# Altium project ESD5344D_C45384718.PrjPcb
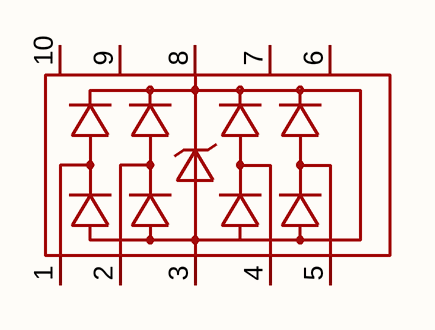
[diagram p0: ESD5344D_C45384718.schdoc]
1 sheet, 1 parts. Net scope: global (net labels, ports and power ports of the same name join across sheets).

## Sheet ESD5344D_C45384718.schdoc
size 127 x 101 mm

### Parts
D?  esd5344d_c45384718  [DFN2510-10_L2.5-W1.0-P0.50-BL]  (value not drawn)

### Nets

Not connected (* = marked no-connect by the designer): D? 1 2 3 4 5 6 7 8 9 10

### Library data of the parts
D? = esd5344d_c45384718: 反向截止电压(Vrwm):5V;钳位电压:15V;击穿电压(VBR):9V;; Manufacturer: JSMSEMI(杰盛微); AddInBom: yes; ModelId: 55525fa8fc914f7c8ffcb10749ea5f73; ModelName: DFN-10_L2.5-W1.0-H0.5-P0.50; ModelTransform: 40.1574,98.425,0,90,0,0,0,0,0; Reverse Stand-Off Voltage (Vrwm): 5V; Clamping Voltage: 15V; Voltage - Breakdown: 9V; Reverse Leakage Current (Ir): 1uA; Number of Channels: 四路; level of protection: IEC 61000-4-4；IEC 61000-4-2; Type: ESD; Junction Capacitance: 0.4pF；0.2pF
